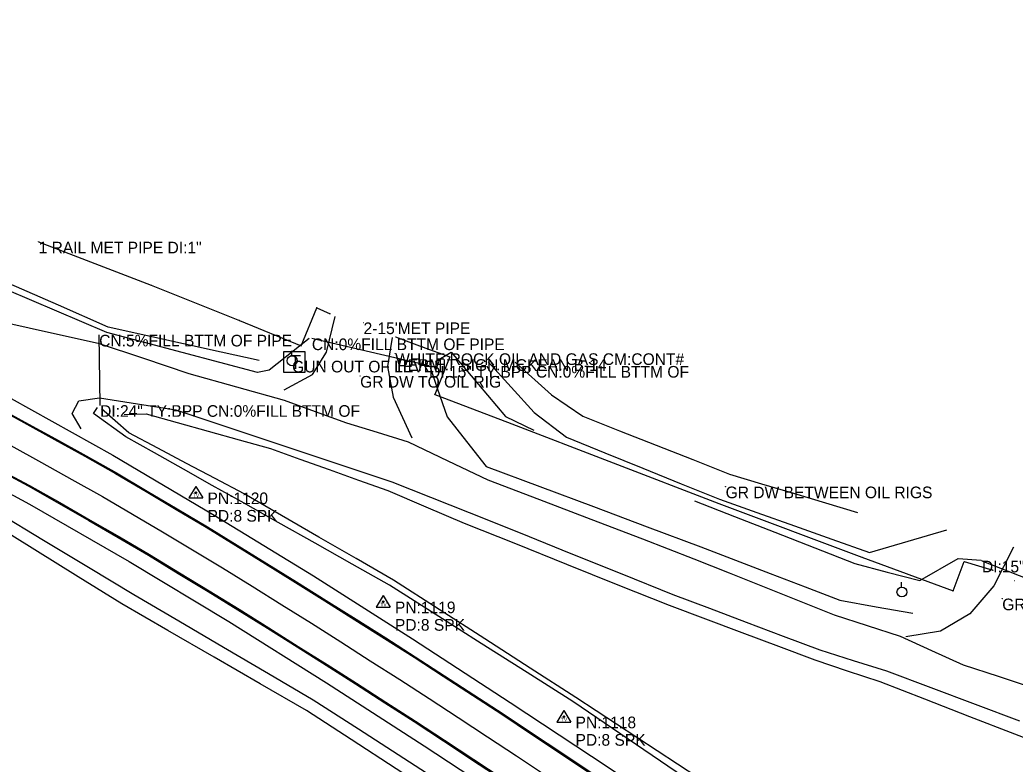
# Model space of a CAD drawing. Extents: x 878399 to 889864, y 1564003 to 1567413.
# Drawn here: x 883093 to 883520.3, y 1566695.3 to 1567014.9 of the extents above; entities that cross this region are included whole.
import ezdxf

# ---------------------------------------------------------------- set-up
doc = ezdxf.new("R2010")
doc.units = 0
for name, color, linetype in [('S_DITCHLINE', 7, 'Continuous'), ('S_DRG_PT_SYM', 7, 'Continuous'), ('S_DRIVEWAY', 7, 'Continuous'), ('S_EDGE_PAVEMENT', 7, 'Continuous'), ('S_FENCE', 7, 'Continuous'), ('S_FENCE_ANNOT', 7, 'Continuous'), ('S_GATE_ANNOT', 7, 'Continuous'), ('S_GRAVEL_ROAD', 7, 'Continuous'), ('S_MSC_PT_SYM', 7, 'Continuous'), ('S_PAVEMENT_CROWN', 7, 'Continuous'), ('S_SECONDARY_CTL', 7, 'Continuous'), ('S_SECONDARY_CTL_ANNOT', 7, 'Continuous'), ('S_SHOULDER', 7, 'Continuous'), ('S_SIDE_DRAIN', 7, 'Continuous'), ('S_SIDE_DRAIN_ANNOT', 7, 'Continuous'), ('S_SURVEY_TEXT_ANNOT', 7, 'Continuous'), ('S_TELEPHONE_UTILITIES', 7, 'Continuous'), ('S_UTILITY_POLE', 7, 'Continuous'), ('S_UTILITY_POLE_ANNOT', 7, 'Continuous')]:
    doc.layers.add(name, color=color, linetype=linetype)

msp = doc.modelspace()

# ---------------------------------------------------------------- linework, layer by layer
at = {"layer": 'S_DITCHLINE'}
for points in [[(883195.7, 1566868.63), (883179.5, 1566872.19), (883163.3, 1566875.75), (883147.1, 1566879.31), (883130.89, 1566882.87), (883109.57, 1566892.3), (883088.24, 1566901.73)], [(883217.24, 1566877.99), (883200.08, 1566864.48), (883195.05, 1566863.42), (883178.88, 1566867.71), (883162.7, 1566871.99), (883146.53, 1566876.27), (883130.36, 1566880.56), (883108.89, 1566889.75), (883087.43, 1566898.94)], [(883271.42, 1566868.24), (883278.24, 1566872.12), (883289.87, 1566858.35), (883301.5, 1566844.57), (883313.76, 1566838.7)], [(883269.16, 1566865.8), (883272.19, 1566856.75), (883276.48, 1566844.38), (883284.82, 1566833.76), (883293.16, 1566823.13), (883316.22, 1566814.5), (883339.27, 1566805.86), (883362.33, 1566797.23), (883385.38, 1566788.6), (883400.31, 1566782.85), (883415.24, 1566777.11), (883430.17, 1566771.36), (883445.1, 1566765.62), (883460.76, 1566762.84), (883476.43, 1566760.06)], [(883381.47, 1566687.35), (883364.48, 1566698.93), (883347.48, 1566710.51), (883330.49, 1566722.09), (883310.79, 1566734.61), (883291.08, 1566747.13), (883271.37, 1566759.66), (883251.67, 1566772.18), (883235.74, 1566781.14), (883219.82, 1566790.11), (883203.9, 1566799.07), (883187.98, 1566808.03), (883175.61, 1566814.99), (883163.24, 1566821.95), (883150.87, 1566828.91), (883138.5, 1566835.87), (883124.65, 1566845.78), (883126.27, 1566848.42)], [(883384.05, 1566689.59), (883366.61, 1566701.01), (883349.18, 1566712.44), (883331.74, 1566723.86), (883312.18, 1566736.46), (883292.62, 1566749.06), (883273.06, 1566761.66), (883253.5, 1566774.26), (883237.44, 1566783.52), (883221.39, 1566792.79), (883205.33, 1566802.05), (883189.27, 1566811.31), (883176.92, 1566817.86), (883164.56, 1566824.41), (883152.21, 1566830.97), (883139.85, 1566837.52), (883128.03, 1566847.78)], [(883137.77, 1566845.44), (883147.28, 1566845.65), (883160.6, 1566841.93), (883173.92, 1566838.2), (883187.23, 1566834.48), (883200.55, 1566830.76), (883213.16, 1566826.26), (883225.77, 1566821.77), (883238.38, 1566817.27), (883250.99, 1566812.78), (883267.38, 1566805.78), (883283.77, 1566798.78), (883305.78, 1566789.96), (883327.78, 1566781.14), (883349.78, 1566772.31), (883371.78, 1566763.49), (883387.43, 1566757.62), (883403.08, 1566751.75), (883418.73, 1566745.88), (883434.38, 1566740.01), (883448.29, 1566735.36), (883462.2, 1566730.71), (883481.49, 1566723.24), (883500.78, 1566715.77), (883520.06, 1566708.29), (883539.35, 1566700.82)], [(883382.74, 1566808.32), (883399.93, 1566801.6), (883417.13, 1566794.88), (883434.32, 1566788.16), (883451.52, 1566781.43), (883465.46, 1566777.76), (883479.39, 1566774.09), (883495.84, 1566783.59), (883505.71, 1566782.85)], [(883437.47, 1566571.9), (883418.53, 1566584.85), (883399.59, 1566597.79), (883380.66, 1566610.74), (883361.72, 1566623.69), (883345.5, 1566635.92), (883329.28, 1566648.15), (883313.06, 1566660.38), (883296.83, 1566672.61), (883277.37, 1566685.14), (883257.91, 1566697.67), (883238.44, 1566710.21), (883218.98, 1566722.74), (883199.72, 1566734.05), (883180.47, 1566745.35), (883161.21, 1566756.66), (883141.96, 1566767.96), (883122.53, 1566779.66), (883103.11, 1566791.36), (883083.69, 1566803.06)], [(883429.46, 1566563.62), (883410.93, 1566577.26), (883392.41, 1566590.89), (883373.89, 1566604.53), (883355.37, 1566618.17), (883339.82, 1566630.64), (883324.27, 1566643.12), (883308.72, 1566655.59), (883293.17, 1566668.06), (883273.89, 1566680.64), (883254.6, 1566693.21), (883235.31, 1566705.78), (883216.02, 1566718.35), (883196.2, 1566729.78), (883176.37, 1566741.21), (883156.54, 1566752.64), (883136.72, 1566764.06), (883118.04, 1566775.65), (883099.36, 1566787.24), (883080.68, 1566798.82)]]:
    msp.add_lwpolyline(points, dxfattribs=at)
at = {"layer": 'S_DRG_PT_SYM'}
for points in [[(883127.06, 1566879.64), (883127.06, 1566879.69), (883127.06, 1566879.64), (883127.01, 1566879.64), (883127.06, 1566879.64), (883127.06, 1566879.59), (883127.06, 1566879.64), (883127.11, 1566879.64)], [(883218.38, 1566878.06), (883218.38, 1566878.11), (883218.38, 1566878.06), (883218.33, 1566878.06), (883218.38, 1566878.06), (883218.38, 1566878.01), (883218.38, 1566878.06), (883218.43, 1566878.06)], [(883268.72, 1566866.25), (883268.72, 1566866.3), (883268.72, 1566866.25), (883268.67, 1566866.25), (883268.72, 1566866.25), (883268.72, 1566866.2), (883268.72, 1566866.25), (883268.77, 1566866.25)], [(883127.45, 1566849.42), (883127.45, 1566849.47), (883127.45, 1566849.42), (883127.4, 1566849.42), (883127.45, 1566849.42), (883127.45, 1566849.37), (883127.45, 1566849.42), (883127.5, 1566849.42)], [(883506.09, 1566782.62), (883506.09, 1566782.67), (883506.09, 1566782.62), (883506.04, 1566782.62), (883506.09, 1566782.62), (883506.09, 1566782.57), (883506.09, 1566782.62), (883506.14, 1566782.62)]]:
    msp.add_lwpolyline(points, dxfattribs=at)
at = {"layer": 'S_DRIVEWAY'}
for points in [[(883206.5, 1566856.07), (883218.6, 1566862.66), (883224.7, 1566872.19), (883228.34, 1566887.5)], [(883252.85, 1566878.42), (883250.92, 1566865.96), (883253.29, 1566852.8), (883261.3, 1566835.46)], [(883519.69, 1566788.45), (883511.15, 1566771.86), (883500.96, 1566759.79), (883488.27, 1566752.39), (883473.47, 1566749.95)]]:
    msp.add_lwpolyline(points, dxfattribs=at)
at = {"layer": 'S_EDGE_PAVEMENT'}
for points in [[(883081.47, 1566849.09), (883094.67, 1566841.96), (883107.81, 1566834.73), (883120.96, 1566827.5), (883120.96, 1566827.5), (883134.02, 1566820.14), (883147.21, 1566812.31), (883160.11, 1566804.65), (883173.01, 1566797), (883185.77, 1566789.11), (883198.53, 1566781.22), (883211.29, 1566773.33), (883224, 1566765.37), (883236.9, 1566757.24), (883249.59, 1566749.24), (883262.25, 1566741.19), (883274.83, 1566733.02), (883287.41, 1566724.85), (883299.99, 1566716.69), (883299.99, 1566716.69), (883299.99, 1566716.69), (883312.69, 1566708.2), (883325.16, 1566699.87), (883337.63, 1566691.53)], [(883081.97, 1566849.3), (883095.17, 1566842.17), (883108.31, 1566834.94), (883121.46, 1566827.72), (883121.46, 1566827.72), (883134.52, 1566820.35), (883147.71, 1566812.52), (883160.61, 1566804.87), (883173.51, 1566797.21), (883186.27, 1566789.33), (883199.03, 1566781.44), (883211.78, 1566773.55), (883224.5, 1566765.59), (883237.4, 1566757.46), (883250.09, 1566749.46), (883262.74, 1566741.41), (883275.32, 1566733.24), (883287.9, 1566725.07), (883300.48, 1566716.9), (883300.48, 1566716.9), (883300.48, 1566716.9), (883313.18, 1566708.42), (883325.65, 1566700.09), (883338.12, 1566691.75)], [(883083.33, 1566821.79), (883096.56, 1566814.71), (883109.63, 1566807.34), (883122.63, 1566799.87), (883122.63, 1566799.87), (883135.27, 1566792.6), (883135.27, 1566792.6), (883135.27, 1566792.6), (883148.2, 1566785), (883161.02, 1566777.2), (883173.83, 1566769.4), (883186.64, 1566761.59), (883199.34, 1566753.61), (883212.04, 1566745.63), (883224.46, 1566737.83), (883237.1, 1566729.75), (883249.71, 1566721.62), (883262.32, 1566713.5), (883274.89, 1566705.31), (883287.4, 1566697.03), (883299.6, 1566688.95)], [(883083.84, 1566822), (883097.06, 1566814.92), (883110.13, 1566807.56), (883123.13, 1566800.08), (883123.13, 1566800.08), (883135.77, 1566792.82), (883135.77, 1566792.82), (883135.77, 1566792.82), (883148.7, 1566785.22), (883161.52, 1566777.42), (883174.33, 1566769.62), (883187.13, 1566761.81), (883199.84, 1566753.83), (883212.54, 1566745.85), (883224.96, 1566738.05), (883237.59, 1566729.97), (883250.2, 1566721.84), (883262.81, 1566713.72), (883275.38, 1566705.53), (883287.89, 1566697.25), (883300.09, 1566689.17)]]:
    msp.add_lwpolyline(points, dxfattribs=at)
at = {"layer": 'S_FENCE'}
for p, q in [((883101.04, 1566919.6), (883149.4, 1566901)), ((883149.4, 1566901), (883187.27, 1566885.72)), ((883213.77, 1566874.92), (883220.49, 1566891.26)), ((883220.49, 1566891.26), (883226.18, 1566888.65)), ((883187.27, 1566885.72), (883213.77, 1566874.92)), ((883254.33, 1566878.79), (883265.72, 1566874.51)), ((883265.72, 1566874.51), (883277.67, 1566870.17)), ((883277.67, 1566870.17), (883271.25, 1566853.95)), ((883271.25, 1566853.95), (883302.42, 1566842.11)), ((883302.42, 1566842.11), (883393.17, 1566807.18)), ((883393.17, 1566807.18), (883454.52, 1566784.21)), ((883454.52, 1566784.21), (883493.72, 1566769.71)), ((883493.72, 1566769.71), (883498.53, 1566782.27)), ((883498.53, 1566782.27), (883510.74, 1566778.5))]:
    msp.add_line(p, q, dxfattribs=at)
at = {"layer": 'S_GRAVEL_ROAD'}
for points in [[(883082.12, 1566885.93), (883096.93, 1566882.62), (883111.74, 1566879.31), (883126.55, 1566876), (883146.02, 1566869.55), (883165.49, 1566863.09), (883185.96, 1566857.33), (883206.43, 1566851.57), (883219.85, 1566846.73), (883233.26, 1566841.88), (883246.46, 1566837.8), (883259.67, 1566833.71), (883276.8, 1566825.52), (883293.93, 1566817.34), (883316.06, 1566808.88), (883338.18, 1566800.41), (883360.31, 1566791.95), (883382.43, 1566783.49), (883397.51, 1566777.45), (883412.58, 1566771.4), (883427.65, 1566765.36), (883442.72, 1566759.32), (883456.87, 1566754.76), (883471.01, 1566750.2), (883484.52, 1566744.04), (883498.03, 1566737.89), (883513.09, 1566732.98), (883528.15, 1566728.08)], [(883294.02, 1566868.1), (883303.96, 1566857.18), (883313.9, 1566846.26), (883327.71, 1566835.68), (883344.12, 1566829.01), (883360.53, 1566822.34), (883376.94, 1566815.68), (883393.35, 1566809.01), (883409.46, 1566803.3), (883425.56, 1566797.59), (883441.67, 1566791.88), (883457.78, 1566786.17), (883474.4, 1566791), (883491.03, 1566795.82)], [(883305.67, 1566867.84), (883321.29, 1566853.81), (883334.78, 1566844.69), (883350.5, 1566838.47), (883366.22, 1566832.24), (883381.94, 1566826.02), (883397.66, 1566819.79), (883411.42, 1566815.67), (883425.18, 1566811.56), (883438.94, 1566807.44), (883452.69, 1566803.33)], [(883119.36, 1566839.21), (883115.52, 1566845.82), (883118.38, 1566851.23), (883127.21, 1566852.6), (883143.56, 1566850.01), (883159.91, 1566847.43), (883180.54, 1566840.54), (883201.17, 1566833.66), (883214.06, 1566829.38), (883226.94, 1566825.11), (883239.83, 1566820.83), (883252.72, 1566816.56), (883269.3, 1566809.94), (883285.89, 1566803.32), (883307.76, 1566794.53), (883329.63, 1566785.74), (883351.5, 1566776.96), (883373.37, 1566768.17), (883389.15, 1566762.2), (883404.93, 1566756.23), (883420.7, 1566750.26), (883436.48, 1566744.3), (883450.8, 1566739.78), (883465.13, 1566735.26), (883484.17, 1566728.13), (883503.2, 1566720.99), (883522.24, 1566713.85)]]:
    msp.add_lwpolyline(points, dxfattribs=at)
at = {"layer": 'S_MSC_PT_SYM'}
for points in [[(883101.04, 1566919.6), (883101.04, 1566919.65), (883101.04, 1566919.6), (883100.99, 1566919.6), (883101.04, 1566919.6), (883101.04, 1566919.55), (883101.04, 1566919.6), (883101.09, 1566919.6)], [(883149.4, 1566901), (883149.4, 1566901.05), (883149.4, 1566901), (883149.35, 1566901), (883149.4, 1566901), (883149.4, 1566900.95), (883149.4, 1566901), (883149.45, 1566901)], [(883220.49, 1566891.26), (883220.49, 1566891.31), (883220.49, 1566891.26), (883220.44, 1566891.26), (883220.49, 1566891.26), (883220.49, 1566891.21), (883220.49, 1566891.26), (883220.54, 1566891.26)], [(883226.18, 1566888.65), (883226.18, 1566888.7), (883226.18, 1566888.65), (883226.13, 1566888.65), (883226.18, 1566888.65), (883226.18, 1566888.6), (883226.18, 1566888.65), (883226.23, 1566888.65)], [(883187.27, 1566885.72), (883187.27, 1566885.77), (883187.27, 1566885.72), (883187.22, 1566885.72), (883187.27, 1566885.72), (883187.27, 1566885.67), (883187.27, 1566885.72), (883187.32, 1566885.72)], [(883240.59, 1566884.94), (883240.59, 1566884.99), (883240.59, 1566884.94), (883240.54, 1566884.94), (883240.59, 1566884.94), (883240.59, 1566884.89), (883240.59, 1566884.94), (883240.64, 1566884.94)], [(883254.33, 1566878.79), (883254.33, 1566878.84), (883254.33, 1566878.79), (883254.28, 1566878.79), (883254.33, 1566878.79), (883254.33, 1566878.74), (883254.33, 1566878.79), (883254.38, 1566878.79)], [(883213.77, 1566874.92), (883213.77, 1566874.97), (883213.77, 1566874.92), (883213.72, 1566874.92), (883213.77, 1566874.92), (883213.77, 1566874.87), (883213.77, 1566874.92), (883213.82, 1566874.92)], [(883254.15, 1566871.69), (883254.15, 1566871.74), (883254.15, 1566871.69), (883254.1, 1566871.69), (883254.15, 1566871.69), (883254.15, 1566871.64), (883254.15, 1566871.69), (883254.2, 1566871.69)], [(883265.72, 1566874.51), (883265.72, 1566874.56), (883265.72, 1566874.51), (883265.67, 1566874.51), (883265.72, 1566874.51), (883265.72, 1566874.46), (883265.72, 1566874.51), (883265.77, 1566874.51)], [(883255.01, 1566869.16), (883255.01, 1566869.21), (883255.01, 1566869.16), (883254.96, 1566869.16), (883255.01, 1566869.16), (883255.01, 1566869.11), (883255.01, 1566869.16), (883255.06, 1566869.16)], [(883277.67, 1566870.17), (883277.67, 1566870.22), (883277.67, 1566870.17), (883277.62, 1566870.17), (883277.67, 1566870.17), (883277.67, 1566870.12), (883277.67, 1566870.17), (883277.72, 1566870.17)], [(883239.11, 1566861.96), (883239.11, 1566862.01), (883239.11, 1566861.96), (883239.06, 1566861.96), (883239.11, 1566861.96), (883239.11, 1566861.91), (883239.11, 1566861.96), (883239.16, 1566861.96)], [(883271.25, 1566853.95), (883271.25, 1566854), (883271.25, 1566853.95), (883271.2, 1566853.95), (883271.25, 1566853.95), (883271.25, 1566853.9), (883271.25, 1566853.95), (883271.3, 1566853.95)], [(883302.42, 1566842.11), (883302.42, 1566842.16), (883302.42, 1566842.11), (883302.37, 1566842.11), (883302.42, 1566842.11), (883302.42, 1566842.06), (883302.42, 1566842.11), (883302.47, 1566842.11)], [(883396.06, 1566814.46), (883396.06, 1566814.51), (883396.06, 1566814.46), (883396.01, 1566814.46), (883396.06, 1566814.46), (883396.06, 1566814.41), (883396.06, 1566814.46), (883396.11, 1566814.46)], [(883393.17, 1566807.18), (883393.17, 1566807.23), (883393.17, 1566807.18), (883393.12, 1566807.18), (883393.17, 1566807.18), (883393.17, 1566807.13), (883393.17, 1566807.18), (883393.22, 1566807.18)], [(883454.52, 1566784.21), (883454.52, 1566784.26), (883454.52, 1566784.21), (883454.47, 1566784.21), (883454.52, 1566784.21), (883454.52, 1566784.16), (883454.52, 1566784.21), (883454.57, 1566784.21)], [(883498.53, 1566782.27), (883498.53, 1566782.32), (883498.53, 1566782.27), (883498.48, 1566782.27), (883498.53, 1566782.27), (883498.53, 1566782.22), (883498.53, 1566782.27), (883498.58, 1566782.27)], [(883510.74, 1566778.5), (883510.74, 1566778.55), (883510.74, 1566778.5), (883510.69, 1566778.5), (883510.74, 1566778.5), (883510.74, 1566778.45), (883510.74, 1566778.5), (883510.79, 1566778.5)], [(883520.16, 1566774.14), (883520.16, 1566774.19), (883520.16, 1566774.14), (883520.11, 1566774.14), (883520.16, 1566774.14), (883520.16, 1566774.09), (883520.16, 1566774.14), (883520.21, 1566774.14)], [(883493.72, 1566769.71), (883493.72, 1566769.76), (883493.72, 1566769.71), (883493.67, 1566769.71), (883493.72, 1566769.71), (883493.72, 1566769.66), (883493.72, 1566769.71), (883493.77, 1566769.71)], [(883514.83, 1566766.34), (883514.83, 1566766.39), (883514.83, 1566766.34), (883514.78, 1566766.34), (883514.83, 1566766.34), (883514.83, 1566766.29), (883514.83, 1566766.34), (883514.88, 1566766.34)]]:
    msp.add_lwpolyline(points, dxfattribs=at)
at = {"layer": 'S_PAVEMENT_CROWN'}
msp.add_lwpolyline([(883089.15, 1566832.14), (883102.25, 1566824.84), (883115.36, 1566817.54), (883128.47, 1566810.25), (883141.36, 1566802.66), (883154.26, 1566795), (883167.16, 1566787.34), (883179.98, 1566779.55), (883192.72, 1566771.63), (883205.46, 1566763.71), (883218.18, 1566755.77), (883230.81, 1566747.73), (883243.46, 1566739.67), (883256.11, 1566731.61), (883268.69, 1566723.44), (883281.25, 1566715.24), (883293.81, 1566707.04), (883306.28, 1566698.79), (883306.28, 1566698.79), (883306.28, 1566698.79), (883318.75, 1566690.45)], dxfattribs=at)
at = {"layer": 'S_SECONDARY_CTL'}
for p, q in [((883168.56, 1566814.52), (883165.55, 1566809.56)), ((883168.56, 1566814.52), (883171.51, 1566809.56)), ((883165.55, 1566809.56), (883171.51, 1566809.56)), ((883249.04, 1566767.67), (883246.03, 1566762.71)), ((883249.04, 1566767.67), (883251.99, 1566762.71)), ((883246.03, 1566762.71), (883251.99, 1566762.71)), ((883326.59, 1566718.28), (883323.58, 1566713.32)), ((883326.59, 1566718.28), (883329.54, 1566713.32)), ((883323.58, 1566713.32), (883329.54, 1566713.32))]:
    msp.add_line(p, q, dxfattribs=at)
for centre, radius in [((883168.56, 1566811.91), 0.311), ((883168.56, 1566811.91), 0.183), ((883168.56, 1566811.91), 0.103), ((883249.04, 1566765.06), 0.311), ((883249.04, 1566765.06), 0.183), ((883249.04, 1566765.06), 0.103), ((883326.59, 1566715.67), 0.311), ((883326.59, 1566715.67), 0.183), ((883326.59, 1566715.67), 0.103)]:
    msp.add_circle(centre, radius, dxfattribs=at)
at = {"layer": 'S_SHOULDER'}
for points in [[(882721.15, 1567014.88), (882768.55, 1566997.45), (882815.33, 1566979.79), (882861.85, 1566960.33), (882907.96, 1566940.99), (882954.18, 1566920.59), (882999.89, 1566898.78), (883044.63, 1566876.45), (883089.22, 1566852.28), (883132.94, 1566828.01), (883176.41, 1566802.24), (883219.06, 1566776.13), (883261.55, 1566749.01), (883303.5, 1566721.79), (883345.59, 1566694), (883386.9, 1566665.83), (883428.02, 1566636.53), (883468.74, 1566606.41), (883508.31, 1566575.84), (883547.66, 1566544.44)], [(882689.13, 1566987.9), (882736.13, 1566970.85), (882782.37, 1566953.35), (882828.37, 1566934.96), (882874.53, 1566915.73), (882919.81, 1566895.88), (882965.22, 1566874.95), (883009.35, 1566853.05), (883053.86, 1566830.25), (883097.13, 1566806.93), (883139.92, 1566782.33), (883182.72, 1566756.47), (883224.64, 1566730.13), (883266.67, 1566703.05), (883307.99, 1566675.86), (883349.44, 1566647.89), (883390.09, 1566619.76), (883430.54, 1566590.36), (883469.72, 1566560.5), (883509.1, 1566529.69), (883547.7, 1566498.51)]]:
    msp.add_lwpolyline(points, dxfattribs=at)
at = {"layer": 'S_SIDE_DRAIN'}
for p, q in [((883127.45, 1566849.42), (883127.06, 1566879.64)), ((883268.72, 1566866.25), (883218.38, 1566878.06)), ((883506.09, 1566782.62), (883535.2, 1566771.15))]:
    msp.add_line(p, q, dxfattribs=at)
at = {"layer": 'S_TELEPHONE_UTILITIES'}
msp.add_lwpolyline([(883206.36, 1566863.49), (883206.36, 1566872.49), (883215.36, 1566872.49), (883215.36, 1566863.49)], close=True, dxfattribs=at)
at = {"layer": 'S_UTILITY_POLE'}
for p, q in [((883209.79, 1566870.63), (883209.79, 1566872.74)), ((883471.62, 1566771.32), (883471.62, 1566773.42))]:
    msp.add_line(p, q, dxfattribs=at)
for centre in [(883209.91, 1566868.49), (883471.75, 1566769.18)]:
    msp.add_circle(centre, 2.13, dxfattribs=at)

# ---------------------------------------------------------------- texts
at = {"layer": 'S_FENCE_ANNOT'}
msp.add_text('1 RAIL MET PIPE DI:1"', height=5, dxfattribs=at).set_placement((883101.04, 1566914.6))
at = {"layer": 'S_GATE_ANNOT'}
msp.add_text("2-15'MET PIPE", height=5, dxfattribs=at).set_placement((883240.59, 1566879.94))
at = {"layer": 'S_SECONDARY_CTL'}
for p in [(883167.36, 1566809.9), (883247.84, 1566763.04), (883325.38, 1566713.66)]:
    msp.add_text('TV', height=1.5, rotation=360, dxfattribs=at).set_placement(p)
at = {"layer": 'S_SECONDARY_CTL_ANNOT'}
for s, p in [('PN:1120', (883173.56, 1566806.91)), ('PD:8 SPK', (883173.56, 1566799.41)), ('PN:1119', (883254.04, 1566760.06)), ('PD:8 SPK', (883254.04, 1566752.56)), ('PN:1118', (883331.59, 1566710.67)), ('PD:8 SPK', (883331.59, 1566703.17))]:
    msp.add_text(s, height=5, dxfattribs=at).set_placement(p)
at = {"layer": 'S_SIDE_DRAIN_ANNOT'}
for s, p in [('CN:5%FILL BTTM OF PIPE', (883127.06, 1566874.64)), ('CN:0%FILL BTTM OF PIPE', (883218.38, 1566873.06)), ('DI:15" TY:BPP CN:0%FILL BTTM OF', (883268.72, 1566861.25)), ('DI:24" TY:BPP CN:0%FILL BTTM OF', (883127.45, 1566844.42)), ('DI:15" TY:BPP CN:0%FILL BTTM OF', (883506.09, 1566777.62))]:
    msp.add_text(s, height=5, dxfattribs=at).set_placement(p)
at = {"layer": 'S_SURVEY_TEXT_ANNOT'}
for s, p in [('WHITE ROCK OIL AND GAS CM:CONT#', (883254.15, 1566866.69)), ('PERMIT SIGN MCKEAN B-14', (883255.01, 1566864.16)), ('GR DW TO OIL RIG', (883239.11, 1566856.96)), ('GR DW BETWEEN OIL RIGS', (883396.06, 1566809.46)), ('GR DW TO OIL WELLS', (883514.83, 1566761.34))]:
    msp.add_text(s, height=5, dxfattribs=at).set_placement(p)
at = {"layer": 'S_TELEPHONE_UTILITIES'}
msp.add_text('T', height=6, rotation=360, dxfattribs=at).set_placement((883208.92, 1566864.99))
at = {"layer": 'S_UTILITY_POLE_ANNOT'}
msp.add_text('GUN OUT OF LEVEL', height=5, dxfattribs=at).set_placement((883209.91, 1566863.49))

doc.saveas('drawing.dxf')
